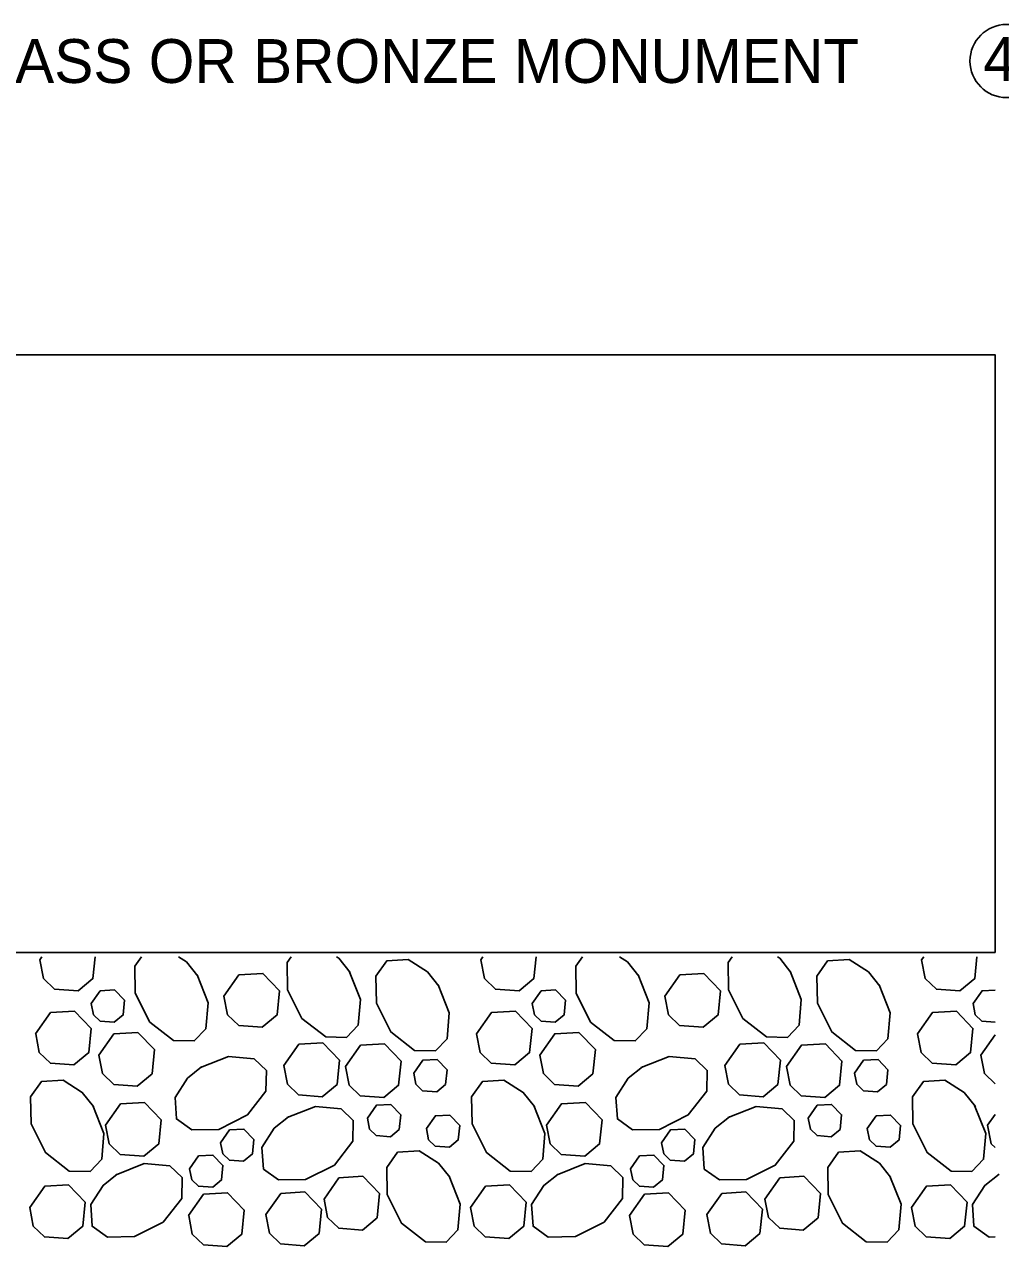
# Model space of a CAD drawing. Extents: x 49991.4 to 50021, y 49987.6 to 50011.4.
# Drawn here: x 50004.182 to 50005.517, y 49995.576 to 49997.247 of the extents above; entities that cross this region are included whole.
import ezdxf

# ---------------------------------------------------------------- set-up
doc = ezdxf.new("R2010")
doc.units = 0
doc.layers.add('Level 1', color=7, linetype='Continuous')
doc.layers.add('Level 2', color=7, linetype='Continuous')

msp = doc.modelspace()

# ---------------------------------------------------------------- linework, layer by layer
at = {"layer": 'Level 1'}
for p, q in [((50004.0592, 49996.7952), (50005.5092, 49996.7952)), ((50003.9448, 49995.9778), (50005.5092, 49995.9778)), ((50004.4044, 49995.9776), (50004.405, 49995.9778)), ((50004.4524, 49995.9778), (50004.4523, 49995.9772))]:
    msp.add_line(p, q, dxfattribs=at)
for points in [[(50005.3097, 49995.9778), (50005.4844, 49995.9778), (50005.5092, 49995.9778), (50005.5092, 49996.7952), (50004.0592, 49996.7952)], [(50004.1035, 49995.9778), (50004.2782, 49995.9778), (50004.3417, 49995.9778), (50004.3924, 49995.9778), (50004.4044, 49995.9778), (50004.4524, 49995.9778), (50004.6084, 49995.9778), (50004.7066, 49995.9778), (50004.8813, 49995.9778), (50004.9448, 49995.9778), (50004.9955, 49995.9778), (50005.2115, 49995.9778), (50005.3097, 49995.9778)], [(50004.2026, 49995.9676), (50004.2055, 49995.9718)], [(50004.2782, 49995.9718), (50004.2752, 49995.942), (50004.255, 49995.9252), (50004.2227, 49995.9276), (50004.2075, 49995.9423), (50004.2026, 49995.9676)], [(50004.4177, 49995.9471), (50004.4329, 49995.9087), (50004.4298, 49995.8735), (50004.4139, 49995.8568), (50004.3853, 49995.8573), (50004.3529, 49995.8827), (50004.3332, 49995.922), (50004.3326, 49995.959), (50004.3417, 49995.9718)], [(50004.3924, 49995.9718), (50004.4032, 49995.9649), (50004.4187, 49995.9455)], [(50004.6259, 49995.952), (50004.6411, 49995.9137), (50004.6381, 49995.8785), (50004.6222, 49995.8617), (50004.5936, 49995.8623), (50004.5611, 49995.8877), (50004.5415, 49995.9269), (50004.5408, 49995.9639), (50004.5464, 49995.9718)], [(50004.6084, 49995.9718), (50004.6115, 49995.9698), (50004.6269, 49995.9505)], [(50004.7474, 49995.9334), (50004.7626, 49995.8951), (50004.7596, 49995.8599), (50004.7437, 49995.8431), (50004.7151, 49995.8437), (50004.6826, 49995.8691), (50004.663, 49995.9083), (50004.6623, 49995.9453), (50004.6771, 49995.9662), (50004.7066, 49995.9681), (50004.733, 49995.9512), (50004.7484, 49995.9319)], [(50004.8057, 49995.9676), (50004.8086, 49995.9718)], [(50004.8813, 49995.9718), (50004.8783, 49995.942), (50004.8581, 49995.9252), (50004.8258, 49995.9276), (50004.8106, 49995.9423), (50004.8057, 49995.9676)], [(50005.0208, 49995.9471), (50005.036, 49995.9087), (50005.0329, 49995.8735), (50005.017, 49995.8568), (50004.9884, 49995.8573), (50004.956, 49995.8827), (50004.9364, 49995.922), (50004.9357, 49995.959), (50004.9448, 49995.9718)], [(50004.9955, 49995.9718), (50005.0063, 49995.9649), (50005.0218, 49995.9455)], [(50005.229, 49995.952), (50005.2442, 49995.9137), (50005.2412, 49995.8785), (50005.2253, 49995.8617), (50005.1967, 49995.8623), (50005.1642, 49995.8877), (50005.1446, 49995.9269), (50005.144, 49995.9639), (50005.1496, 49995.9718)], [(50005.2115, 49995.9718), (50005.2146, 49995.9698), (50005.23, 49995.9505)], [(50005.3505, 49995.9334), (50005.3657, 49995.8951), (50005.3627, 49995.8599), (50005.3468, 49995.8431), (50005.3182, 49995.8437), (50005.2857, 49995.8691), (50005.2661, 49995.9083), (50005.2654, 49995.9453), (50005.2802, 49995.9662), (50005.3097, 49995.9681), (50005.3361, 49995.9512), (50005.3515, 49995.9319)], [(50005.4088, 49995.9676), (50005.4117, 49995.9718)], [(50005.4844, 49995.9718), (50005.4814, 49995.942), (50005.4612, 49995.9252), (50005.4289, 49995.9276), (50005.4137, 49995.9423), (50005.4088, 49995.9676)], [(50004.4545, 49995.9181), (50004.475, 49995.9472), (50004.5077, 49995.9491), (50004.5304, 49995.9255), (50004.5271, 49995.8925), (50004.5069, 49995.8756), (50004.4746, 49995.878), (50004.4594, 49995.8927), (50004.4545, 49995.9181)], [(50005.0576, 49995.9181), (50005.0781, 49995.9472), (50005.1108, 49995.9491), (50005.1335, 49995.9255), (50005.1303, 49995.8925), (50005.11, 49995.8756), (50005.0777, 49995.878), (50005.0625, 49995.8927), (50005.0576, 49995.9181)], [(50004.273, 49995.9079), (50004.2853, 49995.9254), (50004.3049, 49995.9265), (50004.3185, 49995.9124), (50004.3166, 49995.8925), (50004.3044, 49995.8825), (50004.2851, 49995.8839), (50004.2759, 49995.8927), (50004.273, 49995.9079)], [(50004.8761, 49995.9079), (50004.8884, 49995.9254), (50004.908, 49995.9265), (50004.9217, 49995.9124), (50004.9197, 49995.8925), (50004.9076, 49995.8825), (50004.8882, 49995.8839), (50004.8791, 49995.8927), (50004.8761, 49995.9079)], [(50005.4792, 49995.9079), (50005.4915, 49995.9254), (50005.5092, 49995.9264)], [(50004.1968, 49995.8664), (50004.2173, 49995.8956), (50004.25, 49995.8974), (50004.2728, 49995.8739), (50004.2695, 49995.8408), (50004.2493, 49995.824), (50004.217, 49995.8263), (50004.2018, 49995.8411), (50004.1969, 49995.8664)], [(50004.7999, 49995.8664), (50004.8204, 49995.8956), (50004.8531, 49995.8974), (50004.8759, 49995.8739), (50004.8726, 49995.8408), (50004.8524, 49995.824), (50004.8201, 49995.8263), (50004.8049, 49995.8411), (50004.8, 49995.8664)], [(50005.4031, 49995.8664), (50005.4235, 49995.8956), (50005.4563, 49995.8974), (50005.479, 49995.8739), (50005.4757, 49995.8408), (50005.4555, 49995.824), (50005.4232, 49995.8263), (50005.408, 49995.8411), (50005.4031, 49995.8664)], [(50005.5092, 49995.8826), (50005.4913, 49995.8839), (50005.4822, 49995.8927), (50005.4792, 49995.9079)], [(50004.2834, 49995.8375), (50004.3039, 49995.8666), (50004.3366, 49995.8685), (50004.3594, 49995.8449), (50004.3561, 49995.8119), (50004.3359, 49995.7951), (50004.3036, 49995.7974), (50004.2884, 49995.8121), (50004.2834, 49995.8375)], [(50004.8865, 49995.8375), (50004.907, 49995.8666), (50004.9397, 49995.8685), (50004.9625, 49995.8449), (50004.9592, 49995.8119), (50004.939, 49995.7951), (50004.9067, 49995.7974), (50004.8915, 49995.8121), (50004.8865, 49995.8375)], [(50005.4896, 49995.8375), (50005.5092, 49995.8653)], [(50004.5365, 49995.823), (50004.557, 49995.8522), (50004.5897, 49995.8541), (50004.6124, 49995.8305), (50004.6091, 49995.7974), (50004.5889, 49995.7806), (50004.5566, 49995.783), (50004.5414, 49995.7977), (50004.5365, 49995.823)], [(50004.6208, 49995.8218), (50004.6413, 49995.8509), (50004.674, 49995.8528), (50004.6967, 49995.8292), (50004.6934, 49995.7962), (50004.6732, 49995.7794), (50004.6409, 49995.7817), (50004.6257, 49995.7965), (50004.6208, 49995.8218)], [(50005.1396, 49995.823), (50005.1601, 49995.8522), (50005.1928, 49995.8541), (50005.2155, 49995.8305), (50005.2122, 49995.7974), (50005.192, 49995.7806), (50005.1597, 49995.783), (50005.1446, 49995.7977), (50005.1396, 49995.823)], [(50005.2239, 49995.8218), (50005.2444, 49995.8509), (50005.2771, 49995.8528), (50005.2998, 49995.8292), (50005.2966, 49995.7962), (50005.2763, 49995.7794), (50005.244, 49995.7817), (50005.2288, 49995.7965), (50005.2239, 49995.8218)], [(50004.4222, 49995.8204), (50004.4605, 49995.8356), (50004.4957, 49995.8325), (50004.5125, 49995.8166), (50004.5119, 49995.788), (50004.4865, 49995.7556), (50004.4473, 49995.7359), (50004.4103, 49995.7353), (50004.3895, 49995.7501), (50004.3875, 49995.7796), (50004.4044, 49995.8059), (50004.4237, 49995.8213)], [(50004.714, 49995.8128), (50004.7263, 49995.8303), (50004.7459, 49995.8314), (50004.7596, 49995.8172), (50004.7576, 49995.7974), (50004.7455, 49995.7873), (50004.7261, 49995.7888), (50004.717, 49995.7976), (50004.714, 49995.8128)], [(50005.0253, 49995.8204), (50005.0636, 49995.8356), (50005.0988, 49995.8325), (50005.1156, 49995.8166), (50005.115, 49995.788), (50005.0896, 49995.7556), (50005.0504, 49995.7359), (50005.0134, 49995.7353), (50004.9926, 49995.7501), (50004.9906, 49995.7796), (50005.0075, 49995.8059), (50005.0268, 49995.8213)], [(50005.3171, 49995.8128), (50005.3294, 49995.8303), (50005.3491, 49995.8314), (50005.3627, 49995.8172), (50005.3607, 49995.7974), (50005.3486, 49995.7873), (50005.3292, 49995.7888), (50005.3201, 49995.7976), (50005.3171, 49995.8128)], [(50005.5092, 49995.798), (50005.4946, 49995.8121), (50005.4896, 49995.8375)], [(50004.2751, 49995.7686), (50004.2903, 49995.7302), (50004.2873, 49995.695), (50004.2714, 49995.6783), (50004.2428, 49995.6788), (50004.2103, 49995.7042), (50004.1907, 49995.7435), (50004.19, 49995.7805), (50004.2048, 49995.8013), (50004.2343, 49995.8033), (50004.2607, 49995.7864), (50004.2761, 49995.767)], [(50004.8782, 49995.7686), (50004.8934, 49995.7302), (50004.8904, 49995.695), (50004.8745, 49995.6783), (50004.8459, 49995.6788), (50004.8134, 49995.7042), (50004.7938, 49995.7435), (50004.7931, 49995.7805), (50004.8079, 49995.8013), (50004.8374, 49995.8033), (50004.8638, 49995.7864), (50004.8792, 49995.767)], [(50005.4813, 49995.7686), (50005.4965, 49995.7302), (50005.4935, 49995.695), (50005.4776, 49995.6783), (50005.449, 49995.6788), (50005.4165, 49995.7042), (50005.3969, 49995.7435), (50005.3963, 49995.7805), (50005.4111, 49995.8013), (50005.4405, 49995.8033), (50005.4669, 49995.7864), (50005.4823, 49995.767)], [(50004.2925, 49995.7416), (50004.313, 49995.7707), (50004.3457, 49995.7726), (50004.3685, 49995.749), (50004.3652, 49995.716), (50004.345, 49995.6992), (50004.3127, 49995.7015), (50004.2975, 49995.7162), (50004.2925, 49995.7416)], [(50004.5411, 49995.7519), (50004.5795, 49995.7671), (50004.6147, 49995.764), (50004.6314, 49995.7481), (50004.6309, 49995.7196), (50004.6055, 49995.6871), (50004.5662, 49995.6675), (50004.5292, 49995.6668), (50004.5084, 49995.6816), (50004.5064, 49995.7111), (50004.5233, 49995.7374), (50004.5427, 49995.7529)], [(50004.6506, 49995.7513), (50004.6629, 49995.7688), (50004.6825, 49995.7699), (50004.6962, 49995.7558), (50004.6942, 49995.7359), (50004.6821, 49995.7258), (50004.6627, 49995.7273), (50004.6536, 49995.7361), (50004.6506, 49995.7513)], [(50004.8956, 49995.7416), (50004.9161, 49995.7707), (50004.9489, 49995.7726), (50004.9716, 49995.749), (50004.9683, 49995.716), (50004.9481, 49995.6992), (50004.9158, 49995.7015), (50004.9006, 49995.7162), (50004.8957, 49995.7416)], [(50005.1442, 49995.7519), (50005.1826, 49995.7671), (50005.2178, 49995.764), (50005.2345, 49995.7481), (50005.234, 49995.7196), (50005.2086, 49995.6871), (50005.1693, 49995.6675), (50005.1323, 49995.6668), (50005.1115, 49995.6816), (50005.1095, 49995.7111), (50005.1264, 49995.7374), (50005.1458, 49995.7529)], [(50005.2537, 49995.7513), (50005.266, 49995.7688), (50005.2856, 49995.7699), (50005.2993, 49995.7558), (50005.2973, 49995.7359), (50005.2852, 49995.7258), (50005.2658, 49995.7273), (50005.2567, 49995.7361), (50005.2537, 49995.7513)], [(50004.7313, 49995.7369), (50004.7436, 49995.7544), (50004.7632, 49995.7555), (50004.7769, 49995.7413), (50004.7749, 49995.7215), (50004.7628, 49995.7114), (50004.7434, 49995.7128), (50004.7343, 49995.7217), (50004.7313, 49995.7369)], [(50005.3344, 49995.7369), (50005.3467, 49995.7544), (50005.3663, 49995.7555), (50005.38, 49995.7413), (50005.378, 49995.7215), (50005.3659, 49995.7114), (50005.3465, 49995.7128), (50005.3374, 49995.7217), (50005.3344, 49995.7369)], [(50005.4987, 49995.7416), (50005.5092, 49995.7564)], [(50004.4498, 49995.7177), (50004.4621, 49995.7352), (50004.4817, 49995.7363), (50004.4953, 49995.7221), (50004.4934, 49995.7023), (50004.4812, 49995.6922), (50004.4619, 49995.6936), (50004.4527, 49995.7025), (50004.4498, 49995.7177)], [(50005.0529, 49995.7177), (50005.0652, 49995.7352), (50005.0848, 49995.7363), (50005.0984, 49995.7221), (50005.0965, 49995.7023), (50005.0844, 49995.6922), (50005.065, 49995.6936), (50005.0559, 49995.7025), (50005.0529, 49995.7177)], [(50005.5092, 49995.7109), (50005.5037, 49995.7162), (50005.4988, 49995.7416)], [(50004.4075, 49995.6821), (50004.4198, 49995.6996), (50004.4394, 49995.7007), (50004.4531, 49995.6866), (50004.4511, 49995.6668), (50004.439, 49995.6567), (50004.4196, 49995.6581), (50004.4105, 49995.6669), (50004.4075, 49995.6821)], [(50004.7623, 49995.6719), (50004.7775, 49995.6335), (50004.7744, 49995.5983), (50004.7585, 49995.5816), (50004.7299, 49995.5821), (50004.6975, 49995.6075), (50004.6779, 49995.6468), (50004.6772, 49995.6838), (50004.692, 49995.7046), (50004.7215, 49995.7066), (50004.7478, 49995.6897), (50004.7633, 49995.6703)], [(50005.0106, 49995.6821), (50005.0229, 49995.6996), (50005.0425, 49995.7007), (50005.0562, 49995.6866), (50005.0542, 49995.6668), (50005.0421, 49995.6567), (50005.0227, 49995.6581), (50005.0136, 49995.6669), (50005.0106, 49995.6821)], [(50005.3654, 49995.6719), (50005.3806, 49995.6335), (50005.3775, 49995.5983), (50005.3616, 49995.5816), (50005.3331, 49995.5821), (50005.3006, 49995.6075), (50005.281, 49995.6468), (50005.2803, 49995.6838), (50005.2951, 49995.7046), (50005.3246, 49995.7066), (50005.3509, 49995.6897), (50005.3664, 49995.6703)], [(50004.3069, 49995.6738), (50004.3452, 49995.689), (50004.3804, 49995.686), (50004.3971, 49995.67), (50004.3966, 49995.6415), (50004.3712, 49995.609), (50004.332, 49995.5894), (50004.295, 49995.5887), (50004.2741, 49995.6035), (50004.2722, 49995.633), (50004.2891, 49995.6593), (50004.3084, 49995.6748)], [(50004.91, 49995.6738), (50004.9483, 49995.689), (50004.9835, 49995.686), (50005.0002, 49995.67), (50004.9997, 49995.6415), (50004.9743, 49995.609), (50004.9351, 49995.5894), (50004.8981, 49995.5887), (50004.8772, 49995.6035), (50004.8753, 49995.633), (50004.8922, 49995.6593), (50004.9115, 49995.6748)], [(50004.5913, 49995.6406), (50004.6118, 49995.6698), (50004.6445, 49995.6717), (50004.6673, 49995.6481), (50004.664, 49995.615), (50004.6438, 49995.5982), (50004.6115, 49995.6006), (50004.5963, 49995.6153), (50004.5913, 49995.6406)], [(50005.1944, 49995.6406), (50005.2149, 49995.6698), (50005.2476, 49995.6717), (50005.2704, 49995.6481), (50005.2671, 49995.615), (50005.2469, 49995.5982), (50005.2146, 49995.6006), (50005.1994, 49995.6153), (50005.1944, 49995.6406)], [(50005.5092, 49995.5889), (50005.5012, 49995.5887), (50005.4803, 49995.6035), (50005.4784, 49995.633), (50005.4953, 49995.6593), (50005.5146, 49995.6748)], [(50004.1887, 49995.6289), (50004.2092, 49995.658), (50004.2419, 49995.6599), (50004.2646, 49995.6363), (50004.2613, 49995.6033), (50004.2411, 49995.5865), (50004.2088, 49995.5888), (50004.1936, 49995.6035), (50004.1887, 49995.6289)], [(50004.4061, 49995.6181), (50004.4266, 49995.6472), (50004.4593, 49995.6491), (50004.4821, 49995.6255), (50004.4788, 49995.5924), (50004.4586, 49995.5756), (50004.4263, 49995.578), (50004.4111, 49995.5927), (50004.4062, 49995.618)], [(50004.5118, 49995.6193), (50004.5323, 49995.6484), (50004.5651, 49995.6503), (50004.5878, 49995.6267), (50004.5845, 49995.5936), (50004.5643, 49995.5768), (50004.532, 49995.5792), (50004.5168, 49995.5939), (50004.5119, 49995.6193)], [(50004.7918, 49995.6289), (50004.8123, 49995.658), (50004.845, 49995.6599), (50004.8677, 49995.6363), (50004.8645, 49995.6033), (50004.8442, 49995.5865), (50004.8119, 49995.5888), (50004.7967, 49995.6035), (50004.7918, 49995.6289)], [(50005.0092, 49995.6181), (50005.0297, 49995.6472), (50005.0625, 49995.6491), (50005.0852, 49995.6255), (50005.0819, 49995.5924), (50005.0617, 49995.5756), (50005.0294, 49995.578), (50005.0142, 49995.5927), (50005.0093, 49995.618)], [(50005.115, 49995.6193), (50005.1355, 49995.6484), (50005.1682, 49995.6503), (50005.1909, 49995.6267), (50005.1876, 49995.5936), (50005.1674, 49995.5768), (50005.1351, 49995.5792), (50005.1199, 49995.5939), (50005.115, 49995.6193)], [(50005.3949, 49995.6289), (50005.4154, 49995.658), (50005.4481, 49995.6599), (50005.4709, 49995.6363), (50005.4676, 49995.6033), (50005.4474, 49995.5865), (50005.415, 49995.5888), (50005.3999, 49995.6035), (50005.3949, 49995.6289)]]:
    msp.add_lwpolyline(points, dxfattribs=at)
at = {"layer": 'Level 2'}
msp.add_circle((50005.5249, 49997.1968), 0.05, dxfattribs=at)

# ---------------------------------------------------------------- texts
for s, p in [('BRASS OR BRONZE MONUMENT', (50004.0573, 49997.1668)), ('4', (50005.4932, 49997.1697))]:
    msp.add_text(s, height=0.06, dxfattribs=at).set_placement(p)

doc.saveas('drawing.dxf')
